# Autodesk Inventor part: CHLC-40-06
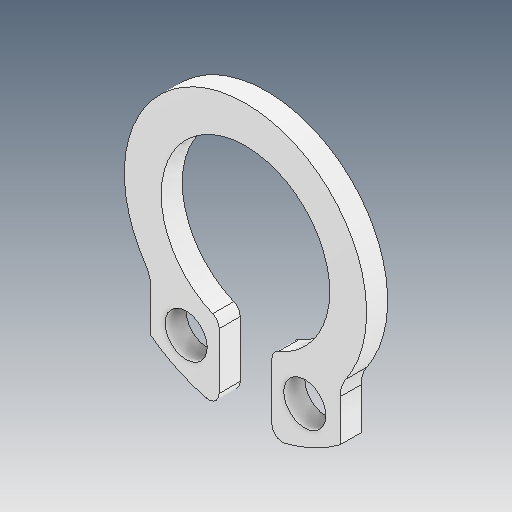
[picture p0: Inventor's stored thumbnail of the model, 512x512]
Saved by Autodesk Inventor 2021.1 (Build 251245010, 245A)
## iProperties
Created: 2021-05
Part Number: CHLC-40-06
Material: Ogólny
Document SubType Name: Modeling
Designer: user
Density: 1 g/cm^3
Appearance: Domyślna
Author: user
Revision Number: ÈÎºÎ
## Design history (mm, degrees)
feature "ÊäÈë1"
node "Bryła1"
